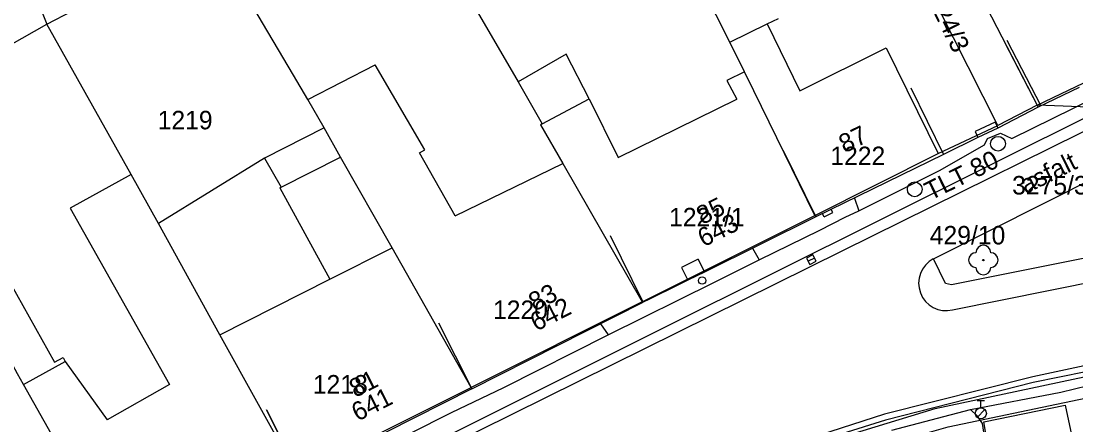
# Model space of a CAD drawing. Extents: x -601580 to 4, y -1204314 to 4.
# Drawn here: x -599820.4 to -599749.1, y -1203397.8 to -1203370.5 of the extents above; entities that cross this region are included whole.
import ezdxf

# ---------------------------------------------------------------- set-up
doc = ezdxf.new("R2010")
doc.units = 0
for name, color, linetype in [('00-KN-HRANICE PARCEL', 7, 'Continuous'), ('00-KN-PARC. CISLA', 7, 'Continuous'), ('00-KN-VNITRNI KRESBA', 7, 'Continuous'), ('00-POLOHOPIS', 7, 'Continuous'), ('00-SITE KOM. KABEL', 7, 'Continuous'), ('00-VAK-VODA-RAD IGIS', 7, 'Continuous'), ('Vrstva 22', 7, 'Continuous'), ('Vrstva 27', 7, 'Continuous'), ('Vrstva 28', 7, 'Continuous')]:
    doc.layers.add(name, color=color, linetype=linetype)

# ---------------------------------------------------------------- blocks, each defined once
blk = doc.blocks.new('6.13_2')
at = {"layer": 'Vrstva 28'}
for p, q in [((-0.25, 0.875), (0.25, 0.875)), ((0, 0.375), (0, 0.875)), ((-0.258, -0.272), (0.272, 0.258))]:
    blk.add_line(p, q, dxfattribs=at)
blk.add_circle((0, 0), 0.375, dxfattribs=at)
blk = doc.blocks.new('3.13_56')
at = {"layer": 'Vrstva 22'}
blk.add_circle((0, 0), 0.05, dxfattribs=at)
for centre, start, end in [((0, 0.5), 0, 180), ((-0.5, 0), 90, 270), ((0.5, 0), 270, 90), ((0, -0.5), 180, 0)]:
    blk.add_arc(centre, 0.5, start, end, dxfattribs=at)
blk = doc.blocks.new('6.30_100')
at = {"layer": 'Vrstva 27'}
blk.add_line((-0.25, 0), (0.25, 0), dxfattribs=at)
blk.add_lwpolyline([(-0.25, -0.25), (0.25, -0.25), (0.25, 0.25), (-0.25, 0.25)], close=True, dxfattribs=at)
blk = doc.blocks.new('6.20D_36')
at = {"layer": 'Vrstva 28'}
blk.add_circle((0, 0), 0.5, dxfattribs=at)
blk = doc.blocks.new('6.14A_170')
at = {"layer": 'Vrstva 28'}
blk.add_circle((0, 0), 0.25, dxfattribs=at)
blk = doc.blocks.new('6.20D_76')
at = {"layer": 'Vrstva 28'}
blk.add_circle((0, 0), 0.5, dxfattribs=at)

msp = doc.modelspace()

# ---------------------------------------------------------------- linework, layer by layer
at = {"layer": '00-KN-HRANICE PARCEL'}
for p, q in [((-599823.55, -1203358.55), (-599818.7, -1203370.73)), ((-599759.18, -1203361.73), (-599751.69, -1203376.22)), ((-599818.7, -1203370.73), (-599811.61, -1203367.05)), ((-599830.21, -1203377.29), (-599818.7, -1203370.73)), ((-599812.99, -1203380.9), (-599818.7, -1203370.73)), ((-599751.69, -1203376.22), (-599746.08, -1203373.51)), ((-599751.69, -1203376.22), (-599754.35, -1203377.58)), ((-599758.39, -1203379.49), (-599754.35, -1203377.58)), ((-599766.74, -1203383.67), (-599758.39, -1203379.49)), ((-599811.15, -1203384.22), (-599812.99, -1203380.9)), ((-599778.42, -1203389.51), (-599766.74, -1203383.67)), ((-599778.42, -1203389.51), (-599789.99, -1203395.3)), ((-599801.77, -1203401.17), (-599789.99, -1203395.3))]:
    msp.add_line(p, q, dxfattribs=at)
for points in [[(-599766.74, -1203383.67), (-599770.87, -1203375.25), (-599771.5, -1203373.97), (-599772.49, -1203371.96), (-599774.35, -1203368.28), (-599779.21, -1203358.64)], [(-599794.22, -1203361.87), (-599790.21, -1203368.78), (-599786.82, -1203374.64)], [(-599799.95, -1203377.75), (-599801.04, -1203375.84), (-599802.01, -1203374.2), (-599807.52, -1203364.89)], [(-599754.35, -1203377.58), (-599759.37, -1203367.68), (-599760.74, -1203364.99)], [(-599746.08, -1203373.51), (-599747.61, -1203376.37), (-599751.69, -1203376.22)], [(-599786.82, -1203374.64), (-599785.18, -1203377.47), (-599785.3, -1203377.54)], [(-599785.3, -1203377.54), (-599783.8, -1203380.15), (-599778.42, -1203389.51)], [(-599799.95, -1203377.75), (-599803.97, -1203379.8), (-599811.15, -1203384.22)], [(-599789.99, -1203395.3), (-599795.35, -1203385.86), (-599798.83, -1203379.73), (-599799.95, -1203377.75)], [(-599801.77, -1203401.17), (-599806.99, -1203391.74), (-599811.15, -1203384.22)], [(-599813.49, -1203407.13), (-599820.29, -1203395.1), (-599820.7, -1203394.37), (-599822.24, -1203391.53), (-599824.48, -1203387.4)]]:
    msp.add_lwpolyline(points, dxfattribs=at)
at = {"layer": '00-KN-VNITRNI KRESBA'}
for p, q in [((-599769.97, -1203370.72), (-599769.21, -1203370.35)), ((-599772.49, -1203371.96), (-599769.97, -1203370.72)), ((-599769.97, -1203370.72), (-599767.75, -1203375.25)), ((-599767.75, -1203375.25), (-599761.92, -1203372.33)), ((-599761.92, -1203372.33), (-599758.39, -1203379.49)), ((-599783.57, -1203372.76), (-599786.82, -1203374.64)), ((-599782, -1203375.79), (-599783.57, -1203372.76)), ((-599801.04, -1203375.84), (-599796.48, -1203373.5)), ((-599793.13, -1203379.24), (-599796.48, -1203373.5)), ((-599771.5, -1203373.97), (-599772.69, -1203374.54)), ((-599772.69, -1203374.54), (-599772.03, -1203375.82)), ((-599785.18, -1203377.47), (-599782, -1203375.79)), ((-599782, -1203375.79), (-599780.04, -1203379.76)), ((-599780.04, -1203379.76), (-599772.03, -1203375.82)), ((-599803.97, -1203379.8), (-599802.85, -1203381.75)), ((-599802.85, -1203381.75), (-599798.83, -1203379.73)), ((-599793.49, -1203379.45), (-599793.13, -1203379.24)), ((-599791.08, -1203383.7), (-599793.49, -1203379.45)), ((-599791.08, -1203383.7), (-599783.8, -1203380.15)), ((-599812.99, -1203380.9), (-599817.12, -1203383.19)), ((-599802.95, -1203381.8), (-599802.85, -1203381.75)), ((-599802.95, -1203381.8), (-599799.55, -1203387.98)), ((-599817.12, -1203383.19), (-599810.4, -1203395.11)), ((-599822.33, -1203386.19), (-599818.18, -1203393.6)), ((-599799.55, -1203387.98), (-599795.35, -1203385.86)), ((-599806.99, -1203391.74), (-599799.55, -1203387.98)), ((-599818.18, -1203393.6), (-599817.61, -1203393.28)), ((-599817.61, -1203393.28), (-599817.46, -1203393.54)), ((-599820.29, -1203395.1), (-599817.46, -1203393.54)), ((-599817.46, -1203393.54), (-599814.62, -1203397.49)), ((-599810.4, -1203395.11), (-599814.62, -1203397.49))]:
    msp.add_line(p, q, dxfattribs=at)
at = {"layer": '00-POLOHOPIS'}
for p, q in [((-599753.928, -1203371.913), (-599751.628, -1203376.352)), ((-599753.751, -1203371.82), (-599751.448, -1203376.266)), ((-599739.906, -1203372.821), (-599776.96, -1203391.264)), ((-599748.848, -1203375.019), (-599751.628, -1203376.352)), ((-599758.725, -1203386.608), (-599739.13, -1203376.771)), ((-599751.628, -1203376.352), (-599754.353, -1203377.764)), ((-599754.546, -1203377.357), (-599755.905, -1203378.001)), ((-599754.546, -1203377.357), (-599754.353, -1203377.764)), ((-599755.904, -1203378), (-599755.706, -1203378.405)), ((-599754.353, -1203377.764), (-599755.706, -1203378.405)), ((-599755.706, -1203378.405), (-599758.042, -1203379.545)), ((-599765.535, -1203383.473), (-599765.636, -1203383.266)), ((-599766.119, -1203383.759), (-599766.22, -1203383.552)), ((-599766.119, -1203383.759), (-599765.535, -1203383.473)), ((-599735.202, -1203383.922), (-599757.49, -1203388.357)), ((-599757.423, -1203390.048), (-599727.284, -1203384.003)), ((-599774.632, -1203386.635), (-599775.754, -1203387.185)), ((-599774.632, -1203386.635), (-599774.207, -1203387.496)), ((-599757.912, -1203388.267), (-599758.725, -1203386.608)), ((-599775.754, -1203387.185), (-599775.331, -1203388.047)), ((-599778.088, -1203389.403), (-599775.761, -1203388.258)), ((-599757.49, -1203388.357), (-599757.912, -1203388.267)), ((-599778.804, -1203389.761), (-599780.232, -1203390.482)), ((-599781.303, -1203391.023), (-599782.33, -1203391.542)), ((-599776.96, -1203391.264), (-599840.166, -1203422.822)), ((-599758.604, -1203396.711), (-599739.643, -1203392.712)), ((-599767.95, -1203399.564), (-599758.604, -1203396.711)), ((-599755.308, -1203397.618), (-599749.803, -1203396.507)), ((-599749.803, -1203396.507), (-599748.481, -1203402.76)), ((-599754.099, -1203404.707), (-599755.308, -1203397.618))]:
    msp.add_line(p, q, dxfattribs=at)
for points in [[(-599760.242, -1203375.055), (-599758.042, -1203379.545), (-599766.669, -1203383.772), (-599768.884, -1203379.289)], [(-599768.884, -1203379.289), (-599766.669, -1203383.772), (-599774.207, -1203387.496), (-599775.331, -1203388.047), (-599778.358, -1203389.536), (-599780.565, -1203385.049)], [(-599792.209, -1203390.93), (-599789.955, -1203395.393), (-599778.358, -1203389.536), (-599780.565, -1203385.049)], [(-599792.209, -1203390.93), (-599789.955, -1203395.393), (-599801.594, -1203401.275), (-599803.853, -1203396.814)], [(-599803.853, -1203396.814), (-599801.594, -1203401.275), (-599813.397, -1203407.253), (-599815.648, -1203402.788)]]:
    msp.add_lwpolyline(points, dxfattribs=at)
msp.add_arc((-599757.871, -1203388.251), 1.852, 117.47695, 283.98519, dxfattribs=at)
at = {"layer": '00-SITE KOM. KABEL'}
for points in [[(-599763.77, -1203383.36), (-599758.31, -1203380.64), (-599755.26, -1203378.9), (-599755.05, -1203378.48), (-599754.18, -1203378.1), (-599753.41, -1203378.48), (-599747.86, -1203375.74), (-599746.17, -1203374.89), (-599745.23, -1203374.45), (-599741.03, -1203372.48), (-599739.53, -1203372.63), (-599739.31, -1203372.6), (-599735.36, -1203371.59), (-599734.61, -1203371.45), (-599733.64, -1203370.79)], [(-599753.41, -1203378.48), (-599747.86, -1203375.74)], [(-599758.31, -1203380.64), (-599755.26, -1203378.9)], [(-599764.07, -1203382.5), (-599763.77, -1203383.36)], [(-599770.5, -1203386.67), (-599766.41, -1203384.66), (-599764.68, -1203383.78), (-599763.77, -1203383.36)], [(-599766.41, -1203384.66), (-599764.68, -1203383.78)], [(-599770.95, -1203385.89), (-599770.5, -1203386.67)], [(-599809.72, -1203418.33), (-599808.56, -1203416.63), (-599800.68, -1203413.33), (-599789.85, -1203409.1), (-599785.82, -1203407.64), (-599785.38, -1203407.07), (-599772.72, -1203402.42), (-599767.04, -1203400.61), (-599757.72, -1203397.96), (-599747.9, -1203395.91), (-599735.74, -1203393.37), (-599714.56, -1203389.17), (-599713.98, -1203388.73), (-599702.01, -1203386.4)], [(-599780.73, -1203391.75), (-599773.52, -1203388.19), (-599770.5, -1203386.67)], [(-599780.73, -1203391.75), (-599773.52, -1203388.19)], [(-599781.24, -1203390.99), (-599780.73, -1203391.75)], [(-599799.88, -1203401.3), (-599791.32, -1203397), (-599787.79, -1203395.3), (-599780.73, -1203391.75)], [(-599756.22, -1203396.79), (-599750.1, -1203395.62), (-599746.4, -1203394.72), (-599744.56, -1203394.34)], [(-599750.1, -1203395.62), (-599746.4, -1203394.72)], [(-599791.32, -1203397), (-599787.79, -1203395.3)], [(-599761.54, -1203398.18), (-599756.22, -1203396.79)], [(-599753.98, -1203404.69), (-599753.99, -1203404.38), (-599754, -1203404.03), (-599754.59, -1203403), (-599755.4, -1203397.74), (-599755.73, -1203397.25), (-599756.22, -1203396.79)], [(-599755.4, -1203397.74), (-599755.73, -1203397.25)]]:
    msp.add_lwpolyline(points, dxfattribs=at)
at = {"layer": '00-VAK-VODA-RAD IGIS'}
for points in [[(-599735.93, -1203391.73), (-599736.05, -1203391.17), (-599737.77, -1203382.75), (-599738.09, -1203382.26), (-599740.66, -1203376.25), (-599742.75, -1203375.13), (-599764.908, -1203386.084), (-599800.54, -1203403.7), (-599828.3, -1203417.77), (-599844.799, -1203426.01), (-599857.174, -1203432.191), (-599857.282, -1203432.244), (-599858.209, -1203432.707), (-599859.333, -1203433.268), (-599861.057, -1203434.129)], [(-599736.917, -1203391.349), (-599751.99, -1203394.59), (-599762.03, -1203397.11), (-599770.82, -1203399.95), (-599780.929, -1203403.567), (-599786.02, -1203405.496), (-599790.989, -1203407.409), (-599793.256, -1203408.295), (-599803.27, -1203412.231), (-599806.056, -1203413.327), (-599817.099, -1203417.917), (-599817.418, -1203418.049), (-599818.78, -1203418.672), (-599820.596, -1203419.503), (-599835.69, -1203426.41), (-599857.929, -1203437.515), (-599863.753, -1203440.423), (-599875.065, -1203446.063), (-599904.229, -1203460.514), (-599915.088, -1203465.894), (-599929.431, -1203473.001), (-599929.758, -1203473.167), (-599936.908, -1203476.866), (-599962.31, -1203490.81)], [(-599735.93, -1203391.73), (-599751.96, -1203394.97), (-599761.97, -1203397.51), (-599770.82, -1203400.29), (-599782.03, -1203404.36), (-599791.55, -1203408.01), (-599806, -1203413.76), (-599817.36, -1203418.46), (-599835.49, -1203426.95), (-599872.84, -1203445.59), (-599889.534, -1203453.919), (-599889.712, -1203454.008), (-599929.34, -1203473.78), (-599935.62, -1203476.92), (-599937.847, -1203473.233), (-599938.29, -1203472.5)]]:
    msp.add_lwpolyline(points, dxfattribs=at)

# ---------------------------------------------------------------- block references
at = {"layer": '00-POLOHOPIS'}
for name, p, xscale, yscale, rotation in [('6.20D_76', (-599754.349, -1203378.824), 1.00000103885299, 1.00000103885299, 117.3284739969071), ('6.20D_36', (-599759.982, -1203381.902), 0.99999966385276, 0.99999966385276, 23.27601388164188), ('6.30_100', (-599766.98, -1203386.661), 0.9999976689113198, 0.9999976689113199, -153.42540330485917)]:
    msp.add_blockref(name, p, dxfattribs=dict(at, xscale=xscale, yscale=yscale, rotation=rotation))
for name, p, rotation in [('3.13_56', (-599755.339, -1203386.69), 180), ('6.14A_170', (-599774.366, -1203388.074), -90.00000000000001)]:
    msp.add_blockref(name, p, dxfattribs=dict(at, rotation=rotation))
msp.add_blockref('6.13_2', (-599755.511, -1203397.049), dxfattribs=at)

# ---------------------------------------------------------------- texts
at = {"layer": '00-KN-PARC. CISLA'}
msp.add_text('1224/3', height=1.25, rotation=296, dxfattribs=at).set_placement((-599759.588, -1203368.179))
for s, p in [('1219', (-599811.207, -1203377.85)), ('1222', (-599765.697, -1203380.27)), ('3275/30', (-599753.394, -1203382.253)), ('1221/1', (-599776.605, -1203384.41)), ('429/10', (-599758.969, -1203385.632)), ('1220', (-599788.517, -1203390.67)), ('1218', (-599800.707, -1203395.71))]:
    msp.add_text(s, height=1.25, dxfattribs=at).set_placement(p)
at = {"layer": '00-POLOHOPIS'}
for s, rotation, p in [('87', 26.10362, (-599764.73, -1203379.481)), ('asfalt', 26.46105, (-599752.47, -1203382.24)), ('85', 26.29076, (-599774.362, -1203384.324)), ('643', 26.29076, (-599774.271, -1203385.831)), ('83', 26.7958, (-599785.703, -1203390.172)), ('642', 26.7958, (-599785.593, -1203391.53)), ('81', 26.81066, (-599797.837, -1203396.015)), ('641', 26.81066, (-599797.684, -1203397.618))]:
    msp.add_text(s, height=1.25, rotation=rotation, dxfattribs=at).set_placement(p)
at = {"layer": '00-VAK-VODA-RAD IGIS'}
msp.add_text('TLT 80', height=1.25, rotation=26.31, dxfattribs=at).set_placement((-599758.922, -1203382.679))

doc.saveas('drawing.dxf')
